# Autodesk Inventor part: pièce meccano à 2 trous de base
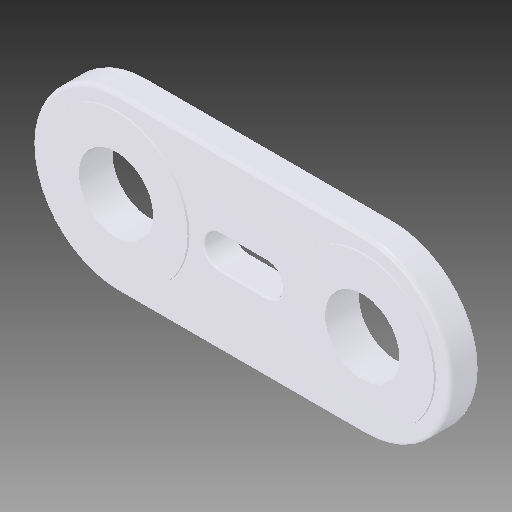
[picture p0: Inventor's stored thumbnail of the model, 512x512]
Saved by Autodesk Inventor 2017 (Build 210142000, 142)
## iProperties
Part Number: pièce meccano à 2 trous de base
Material: Plastique PAEK
Document SubType Name: Modeling
Designer: ficho
Density: 1.32 g/cm^3
Appearance: Blanc froid
Mass: 4.72246 g
Surface Area: 26.3701 cm^2
Volume: 3.57762 cm^3
Author: ficho
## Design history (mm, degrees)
sketch "Esquisse1"
  geometry: L1 (31.5, 11)-(0, 11); L2 (31.5, -11)-(0, -11); A1 r 11 centre (0, 0) between (0, 11) and (0, -11); A2 r 11 centre (31.5, 0) between (31.5, -11) and (31.5, 11); 1 further point
  constraints: 4 end point, 4 point on circle, 4 tangent, 2 centre point, 1 coincident
  dimensions: "d0" = 22 diameter of A1; "d1" = 22 diameter of A2; "d2" = 53.5 dimension on A2 A1
extrude "Extrusion1" new body sketch "Esquisse1" distance "d3" = 3.8; taper "d4" = 0 deg
fillet "Congé1" dims "d5" = 0.5
fillet "Congé2" dims "d6" = 0.5
sketch "Esquisse3"
  geometry: C1 r 9.15 at (0, 0); 1 further point
  constraints: 1 centre point, 1 coincident
  dimensions: "d7" = 18.3 diameter of C1
extrude "Extrusion2" join sketch "Esquisse3" distance "d8" = 0.25; taper "d9" = 0 deg
node "Plan de construction1"
mirror "Symétrie1"
sketch "Esquisse4"
  geometry: 1 further point
hole "Perçage1" sketch "Esquisse4" at (0, 0) diameter "d11" = 9.5; stored, may be unused: countersink angle "d15" = 90 deg, drill point angle "d17" = 118 deg; dims "d12" = 6, "d13" = 4, "d14" = 2, "d16" = 8
pattern_linear "Réseau rectangulaire1" dims "d20" = 31.5
sketch "Esquisse5"
  geometry: L1 (-13, 2)-(-19, 2); L2 (-19, -2)-(-13, -2); A1 r 2 centre (-19, 0) between (-19, 2) and (-19, -2); A2 r 2 centre (-13, 0) between (-13, -2) and (-13, 2); 1 further point
  constraints: 4 end point, 4 point on circle, 4 tangent, 2 centre point
  dimensions: "d21" = 4 diameter of A1; "d22" = 4 diameter of A2 (= d21); "d23" = 6 distance of A2.centre A1.centre; "d24" = 13 distance of point (0, 0) A2.centre
extrude "Extrusion3" cut sketch "Esquisse5" stored distance "d25" = 0.5; taper "d26" = 0 deg
fillet "Congé3" dims "d27" = 0.25
mirror "Symétrie2"
node "Solide1"
other parameters: "d10" = -1.9
